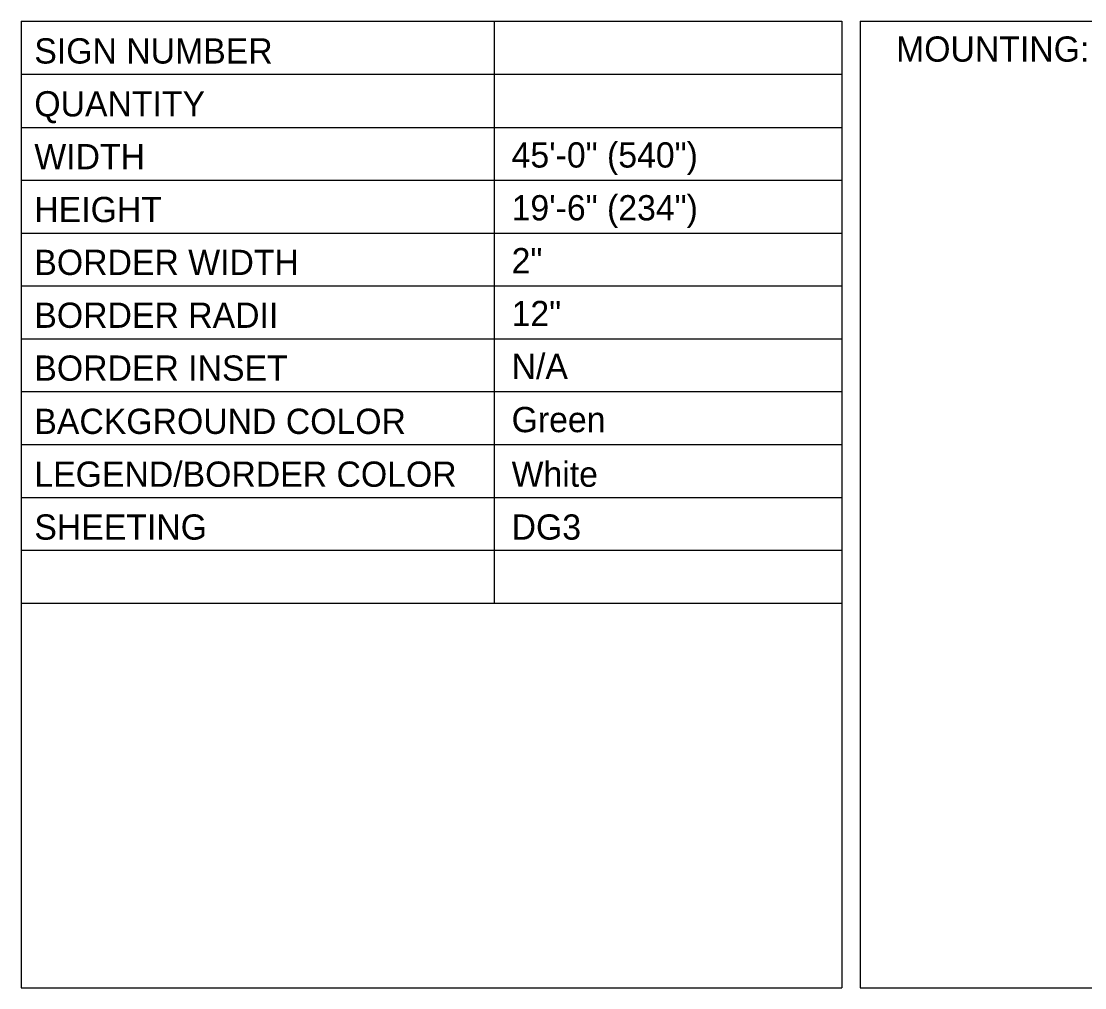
# Model space of a CAD drawing. Extents: x 531799 to 532094, y 1531149 to 1533620.
# Drawn here: x 531804.41 to 531829.46, y 1531174.3 to 1531197.08 of the extents above; entities that cross this region are included whole.
import ezdxf

# ---------------------------------------------------------------- set-up
doc = ezdxf.new("R2010")
doc.units = 0
for name, color, linetype in [('SumBoxLines_dp', 7, 'Continuous'), ('TextLabel', 7, 'Continuous'), ('TextMisc', 7, 'Continuous')]:
    doc.layers.add(name, color=color, linetype=linetype)

msp = doc.modelspace()

# ---------------------------------------------------------------- linework, layer by layer
at = {"layer": 'SumBoxLines_dp'}
for p, q in [((531804.413, 1531197.077), (531804.413, 1531174.302)), ((531804.413, 1531197.077), (531823.746, 1531197.077)), ((531815.556, 1531197.073), (531815.556, 1531183.366)), ((531823.746, 1531197.077), (531823.746, 1531174.302)), ((531824.171, 1531197.077), (531824.171, 1531174.302)), ((531824.171, 1531197.077), (531878.771, 1531197.077)), ((531804.413, 1531195.831), (531823.746, 1531195.831)), ((531804.413, 1531194.577), (531823.746, 1531194.577)), ((531804.413, 1531193.331), (531823.746, 1531193.331)), ((531804.413, 1531192.086), (531823.746, 1531192.086)), ((531804.413, 1531190.84), (531823.746, 1531190.84)), ((531804.413, 1531189.594), (531823.746, 1531189.594)), ((531804.413, 1531188.349), (531823.746, 1531188.349)), ((531804.413, 1531187.103), (531823.746, 1531187.103)), ((531804.413, 1531185.858), (531823.746, 1531185.858)), ((531804.413, 1531184.612), (531823.746, 1531184.612)), ((531804.413, 1531183.366), (531823.746, 1531183.366)), ((531804.413, 1531174.302), (531823.746, 1531174.302)), ((531824.171, 1531174.302), (531878.771, 1531174.302))]:
    msp.add_line(p, q, dxfattribs=at)

# ---------------------------------------------------------------- texts
at = {"layer": 'TextLabel'}
for s, p in [('MOUNTING: OVERHEAD', (531825.021, 1531196.124)), ('45\'-0" (540")', (531815.964, 1531193.629)), ('19\'-6" (234")', (531815.964, 1531192.384)), ('2"', (531815.964, 1531191.138)), ('12"', (531815.964, 1531189.892)), ('N/A', (531815.964, 1531188.647)), ('Green', (531815.964, 1531187.393)), ('White', (531815.964, 1531186.107)), ('DG3', (531815.964, 1531184.861))]:
    msp.add_text(s, height=0.595, dxfattribs=at).set_placement(p)
at = {"layer": 'TextMisc'}
for s, p in [('SIGN NUMBER', (531804.721, 1531196.08)), ('QUANTITY', (531804.721, 1531194.834)), ('WIDTH', (531804.721, 1531193.589)), ('HEIGHT', (531804.721, 1531192.343)), ('BORDER WIDTH', (531804.721, 1531191.098)), ('BORDER RADII', (531804.721, 1531189.852)), ('BORDER INSET', (531804.721, 1531188.606)), ('BACKGROUND COLOR', (531804.721, 1531187.352)), ('LEGEND/BORDER COLOR', (531804.721, 1531186.107)), ('SHEETING', (531804.721, 1531184.861))]:
    msp.add_text(s, height=0.595, dxfattribs=at).set_placement(p)

doc.saveas('drawing.dxf')
